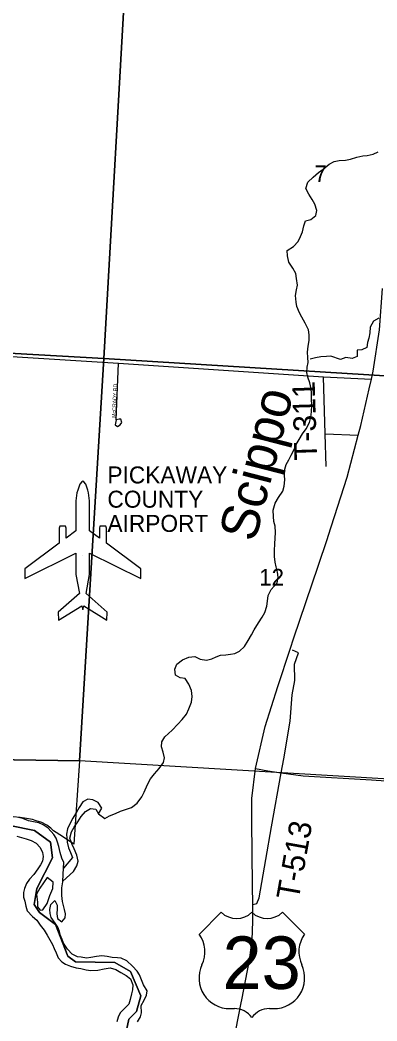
# Model space of a CAD drawing. Extents: x 1643459 to 2064572, y 425441 to 780708.
# Drawn here: x 1831742 to 1836472, y 546559 to 559825 of the extents above; entities that cross this region are included whole.
import ezdxf

# ---------------------------------------------------------------- set-up
doc = ezdxf.new("R2010")
doc.units = 0
for name, color, linetype in [('GM_X_Adjacent_County', 7, 'Continuous'), ('GM_X_Airport_Text_Class_2', 7, 'Continuous'), ('GM_X_Airport_Text_Class_3', 7, 'Continuous'), ('GM_X_City_Street', 7, 'Continuous'), ('GM_X_County', 7, 'Continuous'), ('GM_X_Interchange_Ramps', 7, 'Continuous'), ('GM_X_Interstate_Route', 7, 'Continuous'), ('GM_X_Major_River', 7, 'Continuous'), ('GM_X_Major_River_Text', 7, 'Continuous'), ('GM_X_Minor_River', 7, 'Continuous'), ('GM_X_State_Route', 7, 'Continuous'), ('GM_X_Township', 7, 'Continuous'), ('GM_X_Unincorporated', 7, 'Continuous'), ('GM_X_Unincorporated_Text', 7, 'Continuous'), ('GM_X_US_Route', 7, 'Continuous'), ('RD_X_Text', 7, 'Continuous'), ('RD_X_Wall', 7, 'Continuous'), ('SH_Masking', 7, 'Continuous'), ('SH_Named_Boundary', 7, 'Continuous')]:
    doc.layers.add(name, color=color, linetype=linetype)

msp = doc.modelspace()

# ---------------------------------------------------------------- linework, layer by layer
at = {"layer": 'GM_X_Airport_Text_Class_3'}
msp.add_line((1832573, 552729), (1832573, 552729), dxfattribs=at)
at = {"layer": 'GM_X_City_Street'}
msp.add_lwpolyline([(1833140, 546374), (1833184, 546585), (1833286, 546687), (1833342, 546892), (1833208, 547213), (1833000, 547333), (1832479, 547343), (1832377, 547417), (1832212, 547836), (1832000, 547995), (1831930, 548103), (1831966, 548314), (1832174, 548723), (1832144, 548931), (1831934, 549083), (1831609, 549148)], dxfattribs=at)
at = {"layer": 'GM_X_County'}
msp.add_lwpolyline([(1833015, 554524), (1833001, 554462), (1833032, 554439), (1833071, 554461), (1833089, 554489), (1833079, 554533), (1833055, 554537), (1833016, 554525), (1833048, 555276)], dxfattribs=at)
at = {"layer": 'GM_X_Interstate_Route'}
msp.add_lwpolyline([(1816905, 549626), (1824043, 549269), (1824295, 549255), (1827425, 549078), (1829588, 548977), (1830003, 548861), (1830544, 548899), (1831077, 549092), (1831609, 549148), (1831934, 549083), (1832144, 548931), (1832174, 548723), (1831966, 548314), (1831930, 548103), (1832000, 547995), (1832212, 547836), (1832377, 547417), (1832479, 547343), (1833000, 547333), (1833208, 547213), (1833342, 546892), (1833286, 546687), (1833184, 546585), (1833140, 546374)], dxfattribs=at)
at = {"layer": 'GM_X_Major_River_Text'}
for points in [[(1828875, 555538), (1828877, 555538), (1833048, 555276), (1835763, 555095), (1836399, 555064)], [(1835800, 553908), (1835786, 554341), (1835763, 555095)], [(1835786, 554341), (1836224, 554321)], [(1834825, 548105), (1834881, 548115), (1834912, 548193), (1834999, 548701), (1835074, 549131), (1835204, 549849), (1835237, 550032), (1835322, 550532), (1835349, 550883), (1835382, 551073), (1835381, 551290), (1835431, 551440), (1835351, 551474)]]:
    msp.add_lwpolyline(points, dxfattribs=at)
at = {"layer": 'GM_X_Minor_River'}
msp.add_lwpolyline([(1816905, 549626), (1824043, 549269), (1824295, 549255), (1827425, 549078), (1829588, 548977), (1830003, 548861), (1830544, 548899), (1831077, 549092), (1831609, 549148), (1831934, 549083), (1832144, 548931), (1832174, 548723), (1831966, 548314), (1831930, 548103), (1832000, 547995), (1832212, 547836), (1832377, 547417), (1832479, 547343), (1833000, 547333), (1833208, 547213), (1833342, 546892), (1833286, 546687), (1833184, 546585), (1833140, 546374)], dxfattribs=at)
at = {"layer": 'GM_X_State_Route'}
for points in [[(1827607, 561019), (1833156, 560708), (1832852, 555339), (1827285, 555654)], [(1838604, 560360), (1838314, 555235), (1838298, 555003), (1832852, 555339), (1833156, 560708)], [(1832852, 555339), (1838298, 555003), (1837981, 549774), (1837975, 549683), (1832530, 550005)]]:
    msp.add_lwpolyline(points, close=True, dxfattribs=at)
for points in [[(1827285, 555654), (1832852, 555339), (1832530, 550005), (1828774, 550065)], [(1828774, 550065), (1832530, 550005), (1832455, 548901), (1832303, 549004), (1832186, 549080), (1832150, 549115), (1832098, 549153), (1832030, 549189), (1831954, 549214), (1831906, 549230), (1831803, 549248), (1831745, 549255), (1831651, 549263)]]:
    msp.add_lwpolyline(points, dxfattribs=at)
at = {"layer": 'GM_X_Unincorporated_Text'}
msp.add_line((1832309, 548411), (1832320, 548583), dxfattribs=at)
for points in [[(1832320, 548583), (1832321, 548660), (1832298, 548717), (1832274, 548793), (1832257, 548871), (1832240, 548930), (1832222, 548980), (1832191, 549032), (1832117, 549115), (1832050, 549160), (1831992, 549185), (1831920, 549199), (1831854, 549212), (1831780, 549243), (1831724, 549257)], [(1831700, 549009), (1831762, 548992), (1831825, 548972), (1831889, 548953), (1831957, 548918), (1832009, 548860), (1832042, 548793), (1832048, 548739), (1832039, 548679), (1832012, 548627), (1831978, 548575), (1831923, 548500), (1831866, 548438), (1831826, 548382), (1831803, 548317), (1831787, 548263), (1831788, 548202), (1831804, 548146), (1831819, 548082), (1831838, 548021), (1831906, 547943), (1831965, 547894), (1832009, 547831), (1832060, 547765), (1832100, 547696), (1832135, 547636), (1832171, 547573), (1832194, 547519), (1832220, 547463), (1832247, 547396), (1832295, 547344), (1832346, 547311), (1832410, 547288), (1832488, 547263), (1832548, 547255), (1832618, 547236), (1832682, 547227), (1832772, 547233), (1832856, 547250), (1832935, 547265), (1833012, 547240), (1833078, 547200), (1833148, 547161), (1833208, 547116), (1833239, 547040), (1833232, 546971), (1833218, 546920), (1833201, 546846), (1833186, 546784), (1833070, 546668)], [(1832102, 548459), (1832006, 548320), (1831961, 548238), (1831972, 548134), (1831975, 548071), (1832010, 548027), (1832043, 548032), (1832100, 548116), (1832139, 548222), (1832179, 548313), (1832180, 548399)], [(1832180, 548399), (1832102, 548459)], [(1833352, 546666), (1833348, 546764), (1833389, 546836), (1833418, 546902), (1833426, 546958), (1833379, 547038), (1833352, 547103), (1833324, 547171), (1833293, 547221), (1833233, 547284), (1833158, 547357), (1833084, 547390), (1833032, 547396), (1832964, 547399), (1832898, 547416), (1832826, 547424), (1832754, 547415), (1832680, 547402), (1832621, 547394), (1832553, 547403), (1832503, 547410), (1832434, 547444), (1832370, 547511), (1832319, 547590), (1832299, 547640), (1832278, 547694), (1832264, 547747), (1832243, 547803), (1832207, 547854), (1832156, 547930), (1832142, 547982), (1832137, 548035), (1832150, 548101), (1832204, 548154), (1832234, 548096), (1832235, 548044), (1832230, 547978), (1832240, 547917), (1832296, 547875), (1832340, 547928), (1832343, 547980), (1832331, 548035), (1832316, 548089), (1832304, 548141), (1832295, 548223), (1832295, 548274), (1832298, 548324), (1832309, 548402), (1832309, 548411)], [(1833070, 546668), (1833041, 546608), (1833026, 546546)], [(1833297, 546546), (1833338, 546614), (1833352, 546666)]]:
    msp.add_lwpolyline(points, dxfattribs=at)
at = {"layer": 'GM_X_US_Route'}
for points in [[(1835561, 555501), (1835572, 555577), (1835574, 555651), (1835565, 555718), (1835521, 555806), (1835476, 555885), (1835444, 555945), (1835412, 556026), (1835399, 556086), (1835393, 556172), (1835406, 556247), (1835420, 556311), (1835407, 556397), (1835395, 556465), (1835359, 556536), (1835306, 556616), (1835286, 556699), (1835283, 556769), (1835365, 556825), (1835428, 556891), (1835460, 556955), (1835486, 557017), (1835501, 557097), (1835523, 557163), (1835597, 557181), (1835662, 557232), (1835676, 557300), (1835647, 557383), (1835611, 557447), (1835567, 557516), (1835530, 557590), (1835556, 557674), (1835625, 557740), (1835699, 557802), (1835760, 557850), (1835840, 557914), (1835906, 557951), (1835972, 557961), (1836054, 557966), (1836121, 557982), (1836203, 558006), (1836283, 558025), (1836343, 558029), (1836423, 558048), (1836489, 558078)], [(1836498, 555874), (1836424, 555833), (1836383, 555753), (1836377, 555680), (1836362, 555610), (1836348, 555552), (1836337, 555484), (1836273, 555454), (1836209, 555449), (1836211, 555366), (1836141, 555337), (1836057, 555353), (1835988, 555326), (1835861, 555371), (1835803, 555367), (1835728, 555361), (1835656, 555348), (1835588, 555328)], [(1832784, 549305), (1832868, 549241), (1832926, 549276), (1833008, 549308), (1833075, 549338), (1833139, 549361), (1833219, 549389), (1833295, 549445), (1833356, 549532), (1833388, 549594), (1833433, 549693), (1833471, 549767), (1833526, 549836), (1833586, 549906), (1833643, 549984), (1833657, 550048), (1833638, 550121), (1833618, 550191), (1833623, 550257), (1833663, 550323), (1833756, 550413), (1833832, 550491), (1833892, 550553), (1833949, 550624), (1833977, 550697), (1834016, 550785), (1834024, 550861), (1834013, 550939), (1833979, 551022), (1833932, 551096), (1833864, 551105), (1833804, 551141), (1833792, 551224), (1833821, 551290), (1833897, 551347), (1833980, 551383), (1834058, 551390), (1834127, 551356), (1834215, 551343), (1834284, 551361), (1834342, 551387), (1834400, 551406), (1834470, 551414), (1834530, 551419), (1834588, 551431), (1834648, 551459), (1834717, 551521), (1834765, 551603), (1834810, 551679), (1834846, 551745), (1834901, 551837), (1834951, 551910), (1834984, 551974), (1835014, 552055), (1835020, 552121), (1835031, 552197), (1835071, 552277), (1835150, 552365), (1835164, 552441), (1835155, 552507), (1835135, 552576), (1835122, 552642), (1835116, 552714), (1835115, 552794), (1835117, 552881), (1835124, 552959), (1835128, 553031), (1835123, 553116), (1835103, 553178), (1835099, 553246), (1835098, 553328), (1835124, 553423), (1835167, 553495), (1835223, 553580), (1835244, 553647), (1835250, 553729), (1835247, 553789), (1835249, 553871), (1835270, 553935), (1835302, 553995), (1835334, 554057), (1835377, 554141), (1835403, 554199), (1835440, 554267), (1835484, 554339), (1835533, 554407), (1835577, 554489), (1835596, 554562), (1835604, 554630), (1835607, 554722), (1835605, 554804), (1835603, 554879), (1835600, 554939), (1835584, 555015), (1835557, 555090), (1835543, 555154), (1835546, 555224), (1835558, 555288), (1835554, 555352), (1835553, 555423), (1835561, 555501)], [(1832309, 548411), (1832450, 548541), (1832496, 548615), (1832514, 548679), (1832493, 548755), (1832461, 548840), (1832434, 548900), (1832404, 548983), (1832423, 549067), (1832459, 549127), (1832508, 549197), (1832554, 549271), (1832610, 549337), (1832677, 549376), (1832745, 549368), (1832784, 549305), (1832825, 549379), (1832777, 549454), (1832709, 549492), (1832641, 549497), (1832573, 549463), (1832527, 549389), (1832492, 549327), (1832444, 549249), (1832401, 549171), (1832373, 549105), (1832359, 549035), (1832368, 548929), (1832385, 548852), (1832411, 548794), (1832437, 548726), (1832320, 548583)]]:
    msp.add_lwpolyline(points, dxfattribs=at)
at = {"layer": 'RD_X_Text'}
msp.add_lwpolyline([(1834860, 549906), (1835026, 549875), (1835204, 549849), (1835492, 549807), (1836398, 549757), (1837344, 549691), (1837526, 549687), (1837911, 549728), (1838121, 549769), (1838271, 549771), (1840333, 549617), (1842723, 549434), (1842868, 549331), (1842982, 549150), (1843098, 548902), (1843222, 548762), (1845466, 547998), (1845640, 547766), (1845604, 547129), (1845684, 547011), (1845806, 546916), (1846839, 546852), (1846893, 546849)], dxfattribs=at)
at = {"layer": 'RD_X_Wall'}
for points in [[(1836370, 554935), (1836370, 554935), (1836399, 555064), (1836421, 555173), (1836506, 555718), (1836544, 556267), (1836544, 556268)], [(1835818, 552955), (1835827, 552983), (1836078, 553767), (1836224, 554321), (1836259, 554449), (1836370, 554935)], [(1834681, 546840), (1834781, 547366), (1834819, 547632), (1834829, 547883), (1834825, 548105), (1834821, 548356), (1834812, 549208), (1834812, 549508), (1834860, 549906), (1834991, 550461), (1835159, 550991), (1835321, 551487), (1835370, 551637), (1835692, 552587), (1835818, 552953), (1835818, 552955)], [(1835497, 539034), (1835458, 539654), (1835403, 541669), (1835330, 543133), (1835277, 543456), (1835127, 543925), (1834762, 544909), (1834622, 545571), (1834602, 546438), (1834673, 546800), (1834681, 546840), (1834681, 546840)]]:
    msp.add_lwpolyline(points, dxfattribs=at)
at = {"layer": 'SH_Masking'}
msp.add_lwpolyline([(1832260, 552890), (1831804, 552553), (1831804, 552423), (1832483, 552758), (1832483, 552476), (1832528, 552226), (1832249, 551976), (1832253, 551873), (1832559, 552062), (1832573, 552007), (1832587, 552062), (1832893, 551873), (1832898, 551976), (1832618, 552226), (1832663, 552476), (1832663, 552758), (1833342, 552423), (1833342, 552553), (1832886, 552890), (1832886, 553092), (1832879, 553116), (1832801, 553116), (1832794, 553092), (1832794, 552958), (1832663, 553055), (1832663, 553055), (1832663, 553453), (1832650, 553558), (1832639, 553595), (1832612, 553672), (1832587, 553706), (1832573, 553712), (1832559, 553706), (1832534, 553672), (1832507, 553595), (1832496, 553558), (1832483, 553453), (1832483, 553055), (1832352, 552958), (1832352, 553092), (1832345, 553116), (1832268, 553116), (1832260, 553092)], close=True, dxfattribs=at)
at = {"layer": 'SH_Named_Boundary'}
for p, q in [((1834408, 548000), (1834118, 547710)), ((1835510, 547710), (1835220, 548000)), ((1834524, 546723), (1834582, 546723)), ((1835046, 546723), (1835104, 546723))]:
    msp.add_line(p, q, dxfattribs=at)
for centre, radius, start, end in [((1834611, 548207), 290, 225.573, 314.427), ((1835017, 548207), 290, 225.573, 314.427), ((1833785, 547477), 406, 334.5471, 35.0009), ((1835843, 547477), 406, 144.9991, 205.4529), ((1834519, 547129), 406, 154.8319, 270.6383), ((1835108, 547129), 406, 269.3617, 25.1681), ((1834582, 546433), 290, 36.8699, 90), ((1835046, 546433), 290, 90, 143.1301)]:
    msp.add_arc(centre, radius, start, end, dxfattribs=at)

# ---------------------------------------------------------------- texts
at = {"layer": 'GM_X_Adjacent_County'}
for s, p in [('7', (1835643, 557677)), ('12', (1834911, 552330))]:
    msp.add_text(s, height=221, rotation=0, dxfattribs=at).set_placement(p)
at = {"layer": 'GM_X_Airport_Text_Class_2'}
for s in ['0', '/']:
    msp.add_text(s, height=1, dxfattribs=at).set_placement((1834814, 547327))
msp.add_text('23', height=1, rotation=0, dxfattribs=at).set_placement((1834607, 547120))
at = {"layer": 'GM_X_Interchange_Ramps'}
msp.add_text('Scippo', height=500, rotation=75.532, dxfattribs=at).set_placement((1834856, 552893))
at = {"layer": 'GM_X_Major_River'}
for s, rotation, p in [('T-311', 91.8107, (1835679, 553994)), ('T-513', 79.8459, (1835432, 548149))]:
    msp.add_text(s, height=300, rotation=rotation, dxfattribs=at).set_placement(p)
at = {"layer": 'GM_X_Township'}
msp.add_text('McCRADY RD', height=50, rotation=87.4566, dxfattribs=at).set_placement((1833009, 554551))
at = {"layer": 'GM_X_Unincorporated'}
for s, p in [('PICKAWAY', (1832900, 553683)), ('COUNTY', (1832900, 553362)), ('AIRPORT', (1832900, 553041))]:
    msp.add_text(s, height=225, rotation=0, dxfattribs=at).set_placement(p)
at = {"layer": 'SH_Named_Boundary'}
msp.add_text('23', height=696.1, dxfattribs=at).set_placement((1834426, 546984))

doc.saveas('drawing.dxf')
